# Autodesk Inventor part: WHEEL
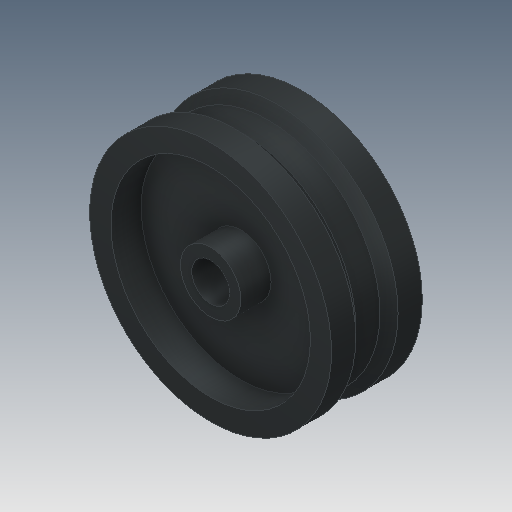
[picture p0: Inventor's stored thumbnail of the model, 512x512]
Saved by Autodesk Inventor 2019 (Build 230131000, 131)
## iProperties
Created: 2016-05
Part Number: WHEEL
Material: Iron, Cast
Document SubType Name: Modeling
Designer: CADCIM
Density: 7.15 g/cm^3
Appearance: Iron Gray
Mass: 68.7858 g
Surface Area: 60.8074 cm^2
Volume: 9.62039 cm^3
Author: CADCIM
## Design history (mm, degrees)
sketch "Sketch1"
  geometry: L1 (0, 0)-(-43, 0); L2 (-20, 3.5)-(-18.5, 2); L3 (-20, -3.5)-(-18.5, -2); L4 (-20, 7.5)-(-20, 3.5); L5 (-20, -3.5)-(-20, -7.5); L6 (-5, 7.5)-(-5, 2.5); L7 (-5, 2.5)-(-16.5, 2.5); L8 (-16.5, 2.5)-(-16.5, 7.5); L9 (-16.5, -7.5)-(-16.5, -2.5); L10 (-16.5, -2.5)-(-5, -2.5); L11 (-5, -2.5)-(-5, -7.5); L12 (-3.125, 7.5)-(-5, 7.5); L13 (-16.5, 7.5)-(-20, 7.5); L14 (-20, -7.5)-(-16.5, -7.5); L15 (-5, -7.5)-(-3.125, -7.5); L16 (0, 7.495)-(0, -7.5); L17 (-3.125, 7.5)-(-3.125, -7.5); L18 (-18.5, 2)-(-18.5, -2); 1 further point
  constraints: 36 end point, 11 perpendicular, 4 collinear, 4 parallel, 4 vertical, 3 horizontal, 2 point on line, 4 other
  dimensions: "d1" = 15 distance of L4.start L5.end; "d2" = 90 deg angle of L3 L2; "d3" = 4 distance of L2.start L4.start; "d4" = 5 distance between parallel lines of L10 L7; "d5" = 6.25 diameter of L17 L16; "d6" = 10 diameter of L11 L16; "d7" = 33 diameter of L9 L16; "d9" = 40 diameter of L4 L16; "d11" = 1.5 distance between parallel lines of L5 L18
revolve "Revolution1" sketch "Sketch1" stored, may be unused: angle "d10" = 90 deg
body "Solid1"
